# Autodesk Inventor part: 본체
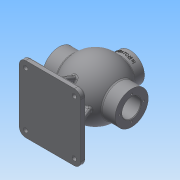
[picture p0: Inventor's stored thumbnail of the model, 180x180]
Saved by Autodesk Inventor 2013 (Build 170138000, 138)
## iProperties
Created: 2018-06
Part Number: 본체
Material: 일반
Document SubType Name: Modeling
Designer: Administrator
Density: 1 g/cm^3
Mass: 557.041 g
Surface Area: 1153.7 cm^2
Volume: 557.041 cm^3
Author: Administrator
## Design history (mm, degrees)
sketch "스케치1"
  geometry: L1 (-68, 0)-(68, 0); L2 (-68, 0)-(-68, 31); L3 (68, 31)-(68, 0); L4 (-68, 31)-(-42.988, 31); L5 (42.988, 31)-(68, 31); A1 r 53 centre (0, 0) between (42.988, 31) and (-42.988, 31); 2 further points
  constraints: 10 end point, 5 perpendicular, 2 coincident, 2 point on circle, 1 centre point, 1 collinear, 1 horizontal, 1 midpoint
  dimensions: "d0" = 106 diameter of A1; "d1" = 136 distance of L1.start L1.end; "d2" = 31 distance of L1.start L2.end
revolve "회전1" sketch "스케치1" stored, may be unused: angle "d3" = 90 deg
sketch "스케치2"
  geometry: L1 (-68, -31)-(-68, 31) reference; L2 (-68, 31)-(-42.988, 31) reference; L3 (42.988, 31)-(68, 31) reference; L4 (68, 31)-(68, -31) reference; L5 (68, -31)-(42.988, -31) reference; L6 (-42.988, -31)-(-68, -31) reference; L7 (-68, 0)-(68, 0); L8 (-68, 0)-(-68, 17.5); L9 (68, 17.5)-(68, 0); L10 (-68, 17.5)-(-39.278, 17.5); L11 (39.278, 17.5)-(68, 17.5); L12 (-52, 18.5)-(-50.25, 18.5); L13 (-50.25, 18.5)-(-50.25, 0); L14 (-50.25, 0)-(-52, 0); L15 (-52, 0)-(-52, 18.5); L16 (-52, 18.5)-(-50.25, 0); L17 (-50.25, 18.5)-(-52, 0); A1 r 43 centre (0, 0) between (39.278, 17.5) and (-39.278, 17.5); A2 r 53 centre (0, 0) between (42.988, 31) and (-42.988, 31) reference; A3 r 53 centre (0, 0) between (-42.988, -31) and (42.988, -31) reference; 4 further points
  constraints: 22 end point, 6 midpoint, 4 perpendicular, 2 parallel, 2 point on circle, 2 point on line, 1 centre point, 1 coincident, 1 collinear, 1 horizontal, 1 horizontal alignment
  dimensions: "d4" = 86 diameter of A1; "d5" = 17.5 distance of L7.start L8.end; "d18" = 1.75 distance of L13.end L14.end; "d19" = 18.5 distance of L12.end L13.end; "d20" = 16 distance between parallel lines of L8 L15
revolve "회전2" sketch "스케치2" stored, may be unused: angle "d6" = 90 deg
sketch "스케치3"
  geometry: L1 (0, 0)-(0, 22.5); C1 r 31 at (0, 0) reference; 1 further point
  constraints: 2 end point, 1 coincident, 1 vertical
  dimensions: "d7" = 22.5 distance of L1.start L1.end
hole "구멍1" sketch "스케치3" at (0, 22.5) diameter "d8" = 3.242; stored, may be unused: countersink angle "d12" = 90 deg, drill point angle "d14" = 118 deg; dims "d9" = 12, "d10" = 4, "d11" = 2, "d13" = 15
sketch "스케치4"
  geometry: L1 (0, 0)-(0, 24); C1 r 31 at (0, 0) reference; 1 further point
  constraints: 2 end point, 1 coincident, 1 vertical
  dimensions: "d21" = 24 distance of L1.start L1.end
hole "구멍2" sketch "스케치4" at (0, 24) diameter "d22" = 3.242; stored, may be unused: countersink angle "d26" = 90 deg, drill point angle "d28" = 118 deg; dims "d23" = 16, "d24" = 4, "d25" = 2, "d27" = 19
node "작업 평면1"
sketch "스케치5"
  geometry: L1 (-57.5, 62.5)-(57.5, 62.5); L2 (57.5, 62.5)-(57.5, -62.5); L3 (57.5, -62.5)-(-57.5, -62.5); L4 (-57.5, -62.5)-(-57.5, 62.5); L5 (-57.5, 62.5)-(57.5, -62.5); L6 (57.5, 62.5)-(-57.5, -62.5); 1 further point
  constraints: 12 end point, 2 midpoint, 2 parallel, 1 horizontal, 1 perpendicular
  dimensions: "d33" = 115 distance of L2.end L3.end; "d34" = 125 distance of L1.end L2.end
extrude "돌출1" join sketch "스케치5" distance "d35" = 10; taper "d36" = 0 deg
sketch "스케치7"
  geometry: L1 (57.5, 62.5)-(-57.5, 62.5) reference; L2 (-4, -52.5)-(4, -52.5); L3 (4, -52.5)-(4, 52.5); L4 (4, 52.5)-(-4, 52.5); L5 (-4, 52.5)-(-4, -52.5); L6 (-4, -52.5)-(4, 52.5); L7 (4, -52.5)-(-4, 52.5); 1 further point
  constraints: 12 end point, 2 midpoint, 2 parallel, 1 horizontal, 1 perpendicular
  dimensions: "d37" = 8 distance of L4.end L3.end; "d38" = 10 distance between parallel lines of L1 L4
extrude "돌출2" join sketch "스케치7" stored distance "d39" = 10; taper "d40" = 0 deg
feature "면 기울기1" dims angle "d41" = 22 deg
sketch "스케치8"
  geometry: L1 (57.5, -62.5)-(57.5, 62.5) reference; L2 (-47.5, 4)-(47.5, 4); L3 (47.5, 4)-(47.5, -4); L4 (47.5, -4)-(-47.5, -4); L5 (-47.5, -4)-(-47.5, 4); L6 (-47.5, 4)-(47.5, -4); L7 (47.5, 4)-(-47.5, -4); 1 further point
  constraints: 12 end point, 2 midpoint, 2 parallel, 1 horizontal, 1 perpendicular
  dimensions: "d42" = 8 distance of L2.end L3.end; "d43" = 10 distance between parallel lines of L1 L3
extrude "돌출3" join sketch "스케치8" stored distance "d44" = 10; taper "d45" = 0 deg
feature "면 기울기2" dims angle "d46" = 22 deg
node "작업 평면2"
sketch "스케치9"
  geometry: C1 r 27 at (0, 0); 1 further point
  constraints: 1 centre point, 1 coincident
  dimensions: "d48" = 54 diameter of C1
extrude "돌출4" join sketch "스케치9" stored distance "d49" = 10; taper "d50" = 0 deg
hole "구멍3" diameter "d53" = 26; stored, may be unused: countersink angle "d57" = 90 deg, drill point angle "d59" = 0 deg; dims "d51" = 10, "d52" = 10, "d54" = 16, "d55" = 4, "d56" = 2, "d58" = 19
sketch "스케치10"
  geometry: L1 (0, 0)-(0, 20); C1 r 13 at (0, 0) reference; 1 further point
  constraints: 2 coincident, 2 end point, 1 vertical
  dimensions: "d60" = 20 distance of L1.start L1.end
hole "구멍4" sketch "스케치10" at (0, 20) diameter "d61" = 3.242; stored, may be unused: countersink angle "d65" = 90 deg, drill point angle "d67" = 118 deg; dims "d62" = 9, "d63" = 4, "d64" = 2, "d66" = 11
fillet "모깎기1" dims "d71" = 12
hole "구멍5" diameter "d74" = 8; stored, may be unused: countersink angle "d78" = 90 deg, drill point angle "d80" = 0 deg; dims "d72" = 10, "d73" = 10, "d75" = 9, "d76" = 12, "d77" = 3, "d79" = 11
chamfer "모따기1" distance "d81" = 1; stored, may be unused: second distance "d82" = 2, angle "d83" = 45 deg
fillet "모깎기2" dims "d84" = 3
fillet "모깎기3" dims "d85" = 3
fillet "모깎기4" dims "d86" = 3
fillet "모깎기5" dims "d87" = 3
node "작업 평면3"
sketch "스케치11"
  geometry: L1 (-50.954, -78)-(-48.622, -78) reference; L2 (-48.622, -78)-(-48.622, -85) reference; L3 (-48.622, -85)-(-57.237, -85) reference; L4 (-57.237, -85)-(-57.237, -78) reference; L5 (-54.146, -75)-(-50.954, -75) reference; L6 (-50.954, -75)-(-50.954, -78) reference; L7 (40.046, -78)-(42.378, -78) reference; L8 (42.378, -78)-(42.378, -85) reference; L9 (42.378, -85)-(-42.378, -85) reference; L10 (-42.378, -85)-(-42.378, -78) reference; L11 (-42.378, -78)-(-40.046, -78) reference; L12 (-40.046, -78)-(-40.046, -75) reference; L13 (-40.046, -75)-(-4.867, -75) reference; L14 (-1, -74.584)-(1, -74.584) reference; L15 (4.867, -75)-(40.046, -75) reference; L16 (40.046, -75)-(40.046, -78) reference; L17 (48.622, -78)-(50.954, -78) reference; L18 (50.954, -78)-(50.954, -75) reference; L19 (50.954, -75)-(54.146, -75) reference; L20 (57.237, -78)-(57.237, -85) reference; L21 (57.237, -85)-(48.622, -85) reference; L22 (48.622, -85)-(48.622, -78) reference; L23 (-27, 65)-(27, 65) reference; 3 further points
  constraints: 1 vertical alignment, 5 other
  dimensions: "d88" = 10 distance from line of L23 point (0, 55)
feature "엠보싱1" sketch "스케치11" dims "d0" = 106, "d1" = 136, "d2" = 31, "d89" = 0.5, "d90" = 0
node "솔리드1"
pattern_circular "원형 패턴1" dims angle "d16" = 360 deg
pattern_circular "원형 패턴2" dims angle "d30" = 360 deg
pattern_circular "원형 패턴3" dims angle "d69" = 360 deg
mirror "대칭1"
mirror "대칭2"
node "절단 모서리 투영1"
node "절단 모서리 투영2"
other parameters: "d32" = -85
